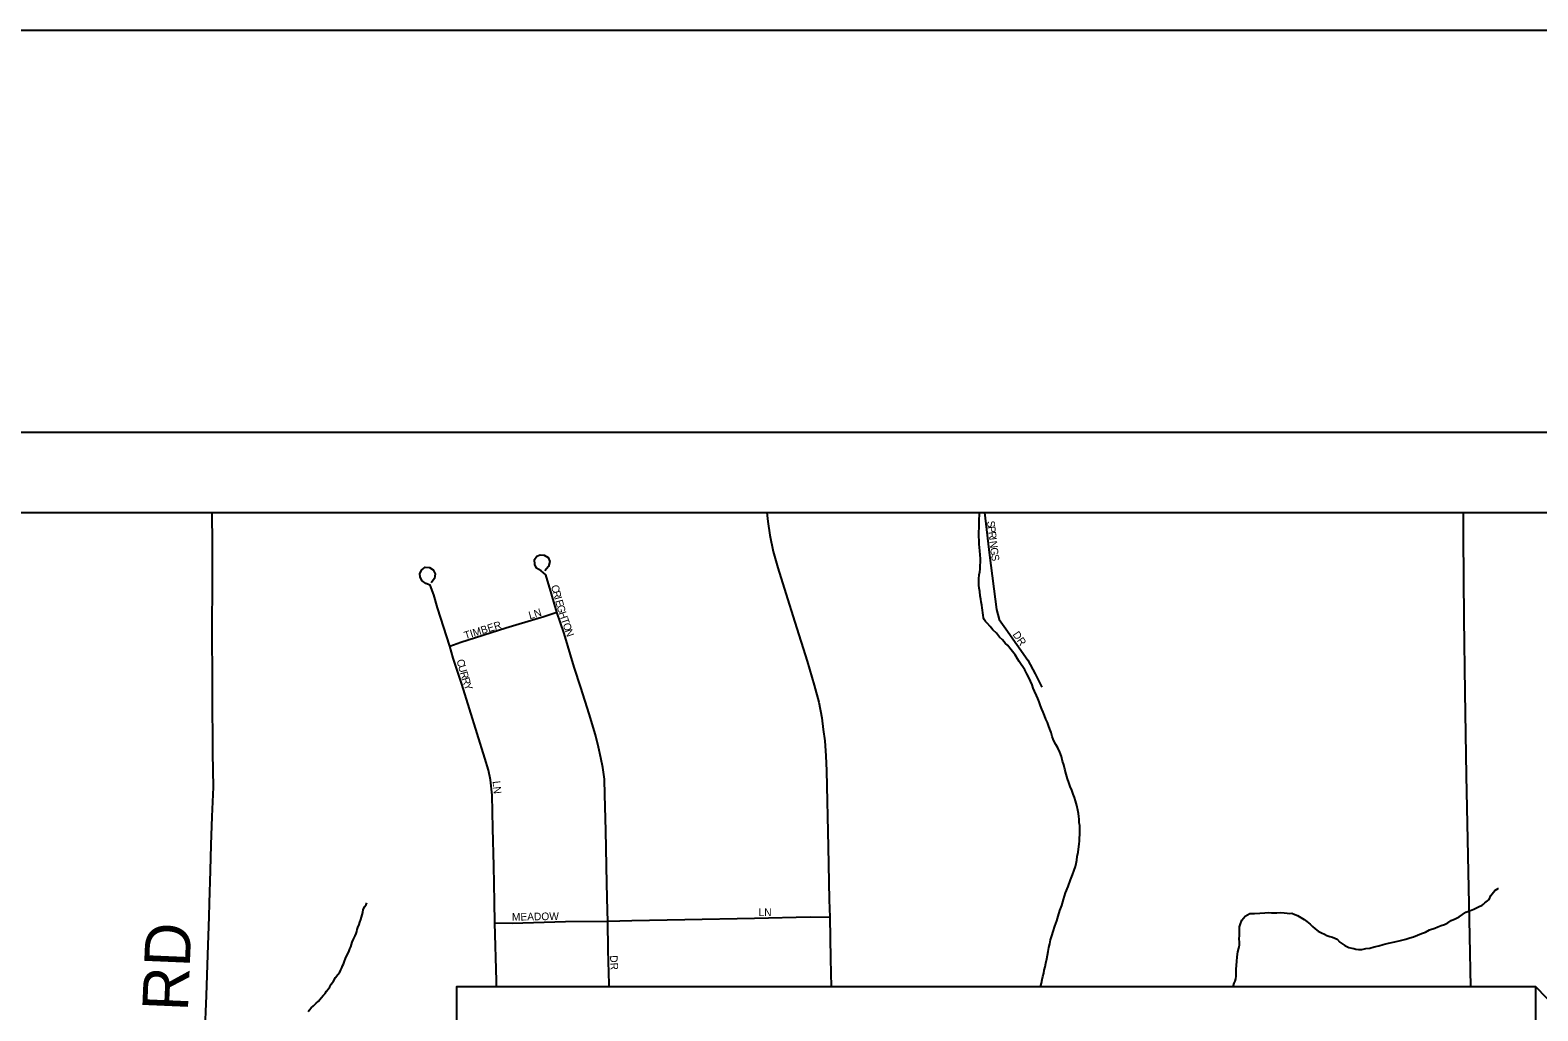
# Model space of a CAD drawing. Extents: x -10.1 to 68, y -9.5 to 29.2.
# Drawn here: x 2.607 to 4.482, y 20.28 to 21.5 of the extents above; entities that cross this region are included whole.
import ezdxf

# ---------------------------------------------------------------- set-up
doc = ezdxf.new("R2010")
doc.units = 0
for name, color, linetype in [('GM_X_County_Road', 7, 'Continuous'), ('GM_X_Minor_River', 7, 'Continuous'), ('GM_X_Township_Road', 7, 'Continuous'), ('GM_X_Township_Road_Text', 7, 'Continuous'), ('GM_X_Township_Subdivision', 7, 'Continuous'), ('GM_X_Township_Subdivision_Text', 7, 'Continuous'), ('SH_Border', 7, 'Continuous'), ('SH_Data', 7, 'Continuous'), ('SH_Text', 7, 'Continuous')]:
    doc.layers.add(name, color=color, linetype=linetype)

msp = doc.modelspace()

# ---------------------------------------------------------------- linework, layer by layer
at = {"layer": 'GM_X_County_Road'}
for points in [[(3.5231, 20.9), (3.5241, 20.8889), (3.5267, 20.8719), (3.531, 20.8514), (3.5365, 20.8312), (3.5467, 20.7993), (3.5578, 20.7636), (3.573, 20.7152), (3.5818, 20.6854), (3.5877, 20.6641), (3.5912, 20.6449), (3.593, 20.6302), (3.595, 20.616), (3.5963, 20.5975), (3.597, 20.5786), (3.5991, 20.4844), (3.6006, 20.4183), (3.6011, 20.3966), (3.6021, 20.3449), (3.6029, 20.31)], [(4.3889, 20.9), (4.389, 20.8698), (4.3898, 20.7678), (4.391, 20.6766), (4.393, 20.5729), (4.3969, 20.373), (4.3981, 20.31)]]:
    msp.add_lwpolyline(points, dxfattribs=at)
at = {"layer": 'GM_X_Minor_River'}
for points in [[(3.9004, 20.5594), (3.8987, 20.5643), (3.8971, 20.5688), (3.8951, 20.5748), (3.8934, 20.5809), (3.8922, 20.5862), (3.8906, 20.5907), (3.8893, 20.5964), (3.8873, 20.602), (3.8849, 20.6073), (3.8825, 20.6114), (3.8805, 20.6152), (3.879, 20.6182), (3.8777, 20.6216), (3.8765, 20.6265), (3.8749, 20.6306), (3.8733, 20.6352), (3.872, 20.6389), (3.8701, 20.6431), (3.8684, 20.6476), (3.8668, 20.6517), (3.8648, 20.6555), (3.8632, 20.6596), (3.8616, 20.6646), (3.86, 20.6687), (3.8584, 20.6725), (3.856, 20.6777), (3.8544, 20.6815), (3.8528, 20.6856), (3.8508, 20.6902), (3.8488, 20.6947), (3.8464, 20.6996), (3.844, 20.7045), (3.8369, 20.7149), (3.8346, 20.7179), (3.8318, 20.7232), (3.8283, 20.7273), (3.8252, 20.7314), (3.8225, 20.7348), (3.8193, 20.7377), (3.8162, 20.7415), (3.8123, 20.7452), (3.8084, 20.75), (3.8042, 20.7541), (3.8006, 20.7582), (3.7975, 20.762), (3.7948, 20.7646), (3.7932, 20.7672), (3.7924, 20.7691), (3.792, 20.7725), (3.7915, 20.7751), (3.7911, 20.7786), (3.7906, 20.7816), (3.7902, 20.785), (3.7897, 20.7888), (3.7893, 20.7922), (3.7884, 20.7964), (3.7879, 20.8017), (3.7871, 20.8058), (3.7866, 20.8096), (3.7865, 20.813), (3.7865, 20.8176), (3.7871, 20.8225), (3.7878, 20.8264), (3.7881, 20.8298), (3.7884, 20.834), (3.7887, 20.8382), (3.7886, 20.8423), (3.7881, 20.8473), (3.788, 20.8522), (3.7875, 20.8564), (3.7871, 20.8606), (3.787, 20.8651), (3.7868, 20.8704), (3.7867, 20.8757), (3.787, 20.8815), (3.7869, 20.8868), (3.7872, 20.8917), (3.7874, 20.8967), (3.7874, 20.9)], [(3.8634, 20.31), (3.8645, 20.3146), (3.8655, 20.3192), (3.8662, 20.323), (3.8673, 20.3272), (3.868, 20.331), (3.869, 20.3352), (3.8701, 20.3394), (3.8711, 20.3451), (3.8721, 20.3494), (3.8728, 20.3539), (3.8738, 20.3589), (3.8749, 20.3635), (3.8759, 20.3684), (3.8773, 20.3734), (3.8791, 20.3791), (3.8812, 20.3857), (3.8838, 20.3922), (3.8855, 20.3979), (3.8873, 20.4052), (3.8898, 20.4113), (3.892, 20.4186), (3.8944, 20.427), (3.8977, 20.435), (3.9006, 20.4431), (3.9031, 20.4496), (3.9052, 20.4553), (3.9067, 20.4599), (3.9077, 20.4634), (3.9084, 20.4676), (3.9091, 20.4721), (3.9101, 20.4775), (3.9114, 20.4878), (3.9117, 20.4912), (3.912, 20.4954), (3.9123, 20.4992), (3.9122, 20.5026), (3.9121, 20.5064), (3.9121, 20.5106), (3.9116, 20.514), (3.9115, 20.5186), (3.9111, 20.522), (3.9106, 20.5258), (3.9097, 20.5299), (3.9085, 20.5356), (3.9068, 20.5413), (3.9056, 20.5454), (3.904, 20.5499), (3.9024, 20.5548), (3.9004, 20.5594)], [(4.1666, 20.4021), (4.17, 20.4018), (4.1734, 20.4015), (4.1761, 20.4016), (4.1796, 20.4001), (4.183, 20.399), (4.1915, 20.3939), (4.1946, 20.3913), (4.1988, 20.388), (4.2016, 20.385), (4.205, 20.3824), (4.2089, 20.3795), (4.2128, 20.3773), (4.2166, 20.3755), (4.2197, 20.374), (4.2231, 20.3729), (4.2266, 20.3719), (4.2296, 20.3708), (4.2323, 20.3693), (4.2358, 20.3656), (4.242, 20.3616), (4.247, 20.359), (4.2504, 20.3583), (4.2531, 20.3576), (4.2554, 20.3569), (4.2588, 20.3566), (4.263, 20.3567), (4.268, 20.3576), (4.2729, 20.3584), (4.2782, 20.3597), (4.2842, 20.361), (4.2895, 20.3626), (4.296, 20.3646), (4.3039, 20.366), (4.3111, 20.3676), (4.3179, 20.3693), (4.3228, 20.3709), (4.3274, 20.3725), (4.3323, 20.3745), (4.3372, 20.3766), (4.3421, 20.3782), (4.347, 20.3809), (4.3538, 20.383), (4.3575, 20.3846), (4.3617, 20.3862), (4.3658, 20.3878), (4.37, 20.3898), (4.3741, 20.3926), (4.379, 20.3949), (4.3839, 20.3973), (4.3884, 20.4001), (4.3925, 20.4028), (4.3963, 20.4044), (4.4001, 20.406), (4.4023, 20.4069), (4.4099, 20.4104), (4.4121, 20.4112), (4.4144, 20.4128), (4.4162, 20.4148), (4.4192, 20.4171), (4.4215, 20.4187), (4.4237, 20.4237), (4.4285, 20.4298), (4.4326, 20.4326), (4.433, 20.4326)], [(2.9525, 20.2796), (2.954, 20.2815), (2.9562, 20.2838), (2.9589, 20.2865), (2.9622, 20.29), (2.9652, 20.2923), (2.9671, 20.2943), (2.9686, 20.2966), (2.9715, 20.2997), (2.9734, 20.302), (2.9753, 20.3047), (2.9771, 20.3073), (2.9794, 20.31), (2.9812, 20.3135), (2.9838, 20.3173), (2.9864, 20.3216), (2.9893, 20.3254), (2.9916, 20.3285), (2.9931, 20.3312), (2.9941, 20.3339), (2.9952, 20.3362), (2.9963, 20.3385), (2.9974, 20.3419), (2.9989, 20.3454), (3.0007, 20.3499), (3.0029, 20.3538), (3.0044, 20.3572), (3.0055, 20.3599), (3.0062, 20.3626), (3.0073, 20.3656), (3.0087, 20.3695), (3.011, 20.3737), (3.012, 20.3764), (3.0128, 20.379), (3.0135, 20.3813), (3.0142, 20.384), (3.0157, 20.3875), (3.0167, 20.3905), (3.0178, 20.394), (3.0203, 20.4024), (3.021, 20.4062), (3.0229, 20.41), (3.0244, 20.4127), (3.0251, 20.4135), (3.0255, 20.4146)], [(4.103, 20.31), (4.1042, 20.3145), (4.1056, 20.3172), (4.1063, 20.3202), (4.1066, 20.3233), (4.1066, 20.3263), (4.1068, 20.3316), (4.1071, 20.337), (4.1074, 20.3415), (4.108, 20.3476), (4.1086, 20.3537), (4.1101, 20.3583), (4.1104, 20.3602), (4.1108, 20.3621), (4.1107, 20.3652), (4.1106, 20.3701), (4.1109, 20.3735), (4.1108, 20.3766), (4.111, 20.3846), (4.1117, 20.3872), (4.1139, 20.393), (4.118, 20.398), (4.1236, 20.4012), (4.1297, 20.4013), (4.1362, 20.4018), (4.1422, 20.4023), (4.1472, 20.4025), (4.1506, 20.4021), (4.154, 20.4022), (4.1574, 20.4023), (4.1616, 20.4024), (4.1666, 20.4021)]]:
    msp.add_lwpolyline(points, dxfattribs=at)
at = {"layer": 'GM_X_Township_Road'}
for points in [[(2.8293, 20.3976), (2.8298, 20.4142), (2.8308, 20.4548), (2.8319, 20.4867), (2.8331, 20.522), (2.8345, 20.5586), (2.8338, 20.6006), (2.8336, 20.6754), (2.8336, 20.6966), (2.8329, 20.7471), (2.8334, 20.8207), (2.8334, 20.8608), (2.833, 20.9)], [(2.8112, 19.5881), (2.8121, 19.6103), (2.8121, 19.6398), (2.8121, 19.6777), (2.8114, 19.7303), (2.8109, 19.8009), (2.8109, 19.8396), (2.8112, 19.8952), (2.8112, 19.9195), (2.8121, 19.9582), (2.8124, 19.971), (2.8133, 19.9929), (2.8145, 20.0259), (2.8157, 20.0743), (2.818, 20.1118), (2.8201, 20.1566), (2.8216, 20.1925), (2.8237, 20.2489), (2.826, 20.2993), (2.8277, 20.3501), (2.8293, 20.3976)]]:
    msp.add_lwpolyline(points, dxfattribs=at)
at = {"layer": 'GM_X_Township_Subdivision'}
for points in [[(3.7935, 20.9), (3.8, 20.8469), (3.8086, 20.7795), (3.8121, 20.7671), (3.8203, 20.7552), (3.8475, 20.7164), (3.8566, 20.6993), (3.8651, 20.6828)], [(3.3267, 20.31), (3.3267, 20.3133), (3.3254, 20.3558), (3.3252, 20.392), (3.3247, 20.4047), (3.3239, 20.4388), (3.3226, 20.5046), (3.3216, 20.5489), (3.3209, 20.5684), (3.3189, 20.5829), (3.3163, 20.5948), (3.3135, 20.6084), (3.3097, 20.6234), (3.3019, 20.6497), (3.2915, 20.6823), (3.2834, 20.7079), (3.271, 20.7497), (3.2619, 20.776), (3.2551, 20.799), (3.248, 20.8226), (3.2424, 20.8274), (3.2366, 20.8307), (3.2343, 20.8355), (3.2341, 20.8415), (3.2368, 20.8456), (3.2411, 20.8474), (3.246, 20.8471), (3.251, 20.8441), (3.2528, 20.8393), (3.2513, 20.8329), (3.2467, 20.8276)], [(3.1866, 20.31), (3.1865, 20.3176), (3.1847, 20.3897), (3.1842, 20.4158), (3.1832, 20.4606), (3.1822, 20.5072), (3.1814, 20.5487), (3.1791, 20.5677), (3.1766, 20.5798), (3.1723, 20.5945), (3.1434, 20.6866), (3.1328, 20.719), (3.1285, 20.734), (3.1133, 20.7816), (3.1088, 20.7978), (3.104, 20.8099), (3.0986, 20.8119), (3.0941, 20.815), (3.0918, 20.8195), (3.0913, 20.8241), (3.0936, 20.8289), (3.0981, 20.8319), (3.1034, 20.8317), (3.108, 20.8289), (3.1103, 20.8238), (3.1095, 20.818), (3.1052, 20.8127)], [(3.1285, 20.734), (3.1424, 20.7388), (3.1981, 20.7565), (3.2383, 20.7685), (3.2454, 20.7707), (3.2619, 20.776)], [(3.1847, 20.3897), (3.2062, 20.3895), (3.2725, 20.3915), (3.3252, 20.392), (3.355, 20.3928), (3.4211, 20.3938), (3.5074, 20.3956), (3.5768, 20.3971), (3.6011, 20.3966)]]:
    msp.add_lwpolyline(points, dxfattribs=at)
at = {"layer": 'SH_Border'}
msp.add_lwpolyline([(1.5, 21.5), (33.5, 21.5), (33.5, 0.5), (1.5, 0.5)], close=True, dxfattribs=at)
at = {"layer": 'SH_Data'}
for p, q in [((2, 21), (9, 21)), ((2.1, 20.9), (8.9, 20.9))]:
    msp.add_line(p, q, dxfattribs=at)
at = {"layer": 'SH_Text'}
for points in [[(3.137, 19.8164), (4.4795, 19.8164), (4.4795, 20.31), (3.137, 20.31)], [(5.1794, 19.5875), (4.4795, 19.82), (4.4795, 20.31)]]:
    msp.add_lwpolyline(points, close=True, dxfattribs=at)

# ---------------------------------------------------------------- texts
at = {"layer": 'GM_X_Township_Road_Text'}
msp.add_text('RD', height=0.05682, rotation=87.552, dxfattribs=at).set_placement((2.8027, 20.279))
at = {"layer": 'GM_X_Township_Subdivision_Text'}
for s, rotation, p in [('S', 276.7354, (3.7968, 20.8892)), ('P', 276.7354, (3.7976, 20.8826)), ('R', 276.7184, (3.7984, 20.8759)), ('I', 276.7382, (3.7993, 20.8685)), ('N', 276.7439, (3.7998, 20.8643)), ('G', 277.1196, (3.8007, 20.856)), ('S', 279.6071, (3.8018, 20.8473)), ('C', 285.762, (3.2543, 20.8086)), ('R', 285.77, (3.2563, 20.8014)), ('N', 17.7423, (3.2349, 20.7692)), ('I', 285.7878, (3.2584, 20.7941)), ('E', 285.7728, (3.2595, 20.7901)), ('G', 286.4761, (3.2613, 20.7836)), ('TIMBER', 17.024, (3.1479, 20.7423)), ('L', 14.7783, (3.228, 20.7673)), ('H', 288.8405, (3.2638, 20.7752)), ('T', 289.2593, (3.2665, 20.7672)), ('O', 289.2964, (3.2688, 20.7609)), ('N', 289.2964, (3.2715, 20.7531)), ('DR', 304.508, (3.8282, 20.7483)), ('C', 285.9921, (3.1368, 20.7161)), ('U', 285.9874, (3.1388, 20.7089)), ('R', 285.9921, (3.1411, 20.7009)), ('R', 287.1609, (3.1433, 20.6935)), ('Y', 290.4734, (3.1457, 20.6858)), ('LN', 275.7182, (3.1818, 20.5658)), ('LN', 0, (3.5126, 20.3982)), ('MEADOW', 0.8947, (3.2059, 20.3924)), ('DR', 273.0225, (3.3277, 20.3491))]:
    msp.add_text(s, height=0.00947, rotation=rotation, dxfattribs=at).set_placement(p)

doc.saveas('drawing.dxf')
